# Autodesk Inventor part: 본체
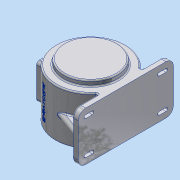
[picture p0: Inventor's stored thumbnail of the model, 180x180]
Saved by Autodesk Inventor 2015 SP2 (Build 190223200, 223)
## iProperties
Created: 2015-06
Part Number: 본체
Material: 알루미늄 6061
Document SubType Name: Modeling
Designer: AMC
Density: 2.7 g/cm^3
Appearance: 알루미늄 - 평지
Mass: 3261.98 g
Surface Area: 2301.65 cm^2
Volume: 1208.14 cm^3
Author: AMC
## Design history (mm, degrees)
sketch "스케치1"
  geometry: C1 r 85 at (0, 0); 1 further point
  constraints: 1 centre point, 1 coincident
  dimensions: "d0" = 170 diameter of C1
extrude "돌출1" new body sketch "스케치1" distance "d1" = 118; taper "d2" = 0 deg
sketch "스케치2"
  geometry: C1 r 65 at (0, 0); 1 further point
  constraints: 1 centre point, 1 coincident
  dimensions: "d3" = 130 diameter of C1
extrude "돌출2" join sketch "스케치2" distance "d4" = 13; taper "d5" = 0 deg
sketch "스케치3"
  geometry: L1 (71, -115)-(85, -115); L2 (85, -115)-(85, 115); L3 (85, 115)-(71, 115); L4 (71, 115)-(71, -115); C1 r 65 at (0, 0) reference; C2 r 85 at (0, 0) reference; C3 r 65 at (0, 0) reference; 3 further points
  constraints: 8 end point, 2 parallel, 1 coincident, 1 horizontal, 1 horizontal alignment, 1 midpoint, 1 perpendicular
  dimensions: "d6" = 230 distance of L3.end L1.start; "d7" = 14 distance of L2.end L3.end; "d8" = 85 distance from line of L2 point (0, 0)
extrude "돌출3" join sketch "스케치3" distance "d9" = 118; taper "d10" = 0 deg
node "작업 평면1"
sketch "스케치4"
  geometry: L1 (71, -115)-(71, -46.733) reference; L2 (71, 46.733)-(71, 115) reference; L3 (71, 115)-(85, 115) reference; L4 (85, 115)-(85, -115) reference; L5 (85, -115)-(71, -115) reference; L6 (71, -109)-(39.218, -97.432); A1 r 85 centre (0, 0) between (71, 46.733) and (71, -46.733) reference; 1 further point
  constraints: 2 end point, 1 point on line
  dimensions: "d11" = 6 distance from line of L5 L6.start; "d12" = 110 deg angle of L1 L6
feature "리브1" sketch "스케치4" dims "d13" = 1, "d14" = 15, "d15" = 0, "d16" = 0, "d17" = 1, "d18" = 1
node "작업 평면2"
sketch "스케치5"
  geometry: C1 r 65 at (0, 0); 1 further point
  constraints: 1 centre point, 1 coincident
  dimensions: "d19" = 130 diameter of C1
extrude "돌출4" join sketch "스케치5" distance "d20" = 3; taper "d21" = 0 deg
fillet "모깎기1" dims "d22" = 2
sketch "스케치6"
  geometry: C1 r 47.5 at (0, 0); 1 further point
  constraints: 1 centre point, 1 coincident
  dimensions: "d23" = 95 diameter of C1
extrude "돌출5" cut sketch "스케치6" distance "d24" = 11; taper "d25" = 0 deg
node "작업 평면3"
sketch "스케치7"
  geometry: L1 (-4, 118)-(14, 118) reference; L2 (14, 118)-(14, 0) reference; L3 (14, 0)-(-6, 0) reference; L4 (-6, 0)-(-6, -13) reference; L5 (-6, -13)-(-136, -13) reference; L6 (-136, -13)-(-136, 0) reference; L7 (-136, 0)-(-156, 0) reference; L8 (-156, 0)-(-156, 118) reference; L9 (-156, 118)-(-138, 118) reference; L10 (-136, 120)-(-136, 121) reference; L11 (-136, 121)-(-118.5, 121) reference; L12 (-118.5, 121)-(-118.5, 110) reference; L13 (-118.5, 110)-(-23.5, 110) reference; L14 (-23.5, 110)-(-23.5, 121) reference; L15 (-23.5, 121)-(-6, 121) reference; L16 (-6, 121)-(-6, 120) reference; L17 (-6, 121)-(-136, 121) reference; L18 (-71, -13)-(-71, 136.664); L19 (-148, 8)-(-71, 8); L20 (-71, 8)-(-71, 110); L21 (-71, 110)-(-148, 110); L22 (-148, 110)-(-148, 8); A1 r 2 centre (-4, 120) between (-6, 120) and (-4, 118) reference; A2 r 2 centre (-138, 120) between (-138, 118) and (-136, 120) reference; 1 further point
  constraints: 10 end point, 2 midpoint, 2 parallel, 1 horizontal, 1 perpendicular, 1 point on line, 1 vertical
  dimensions: "d32" = 8 distance between parallel lines of L8 L22; "d33" = 8 distance between parallel lines of L7 L19
revolve "회전1" sketch "스케치7" stored, may be unused: angle "d34" = 90 deg
sketch "스케치8"
  geometry: C1 r 31 at (0, 0); 1 further point
  constraints: 1 centre point, 1 coincident
  dimensions: "d35" = 62 diameter of C1
extrude "돌출6" join sketch "스케치8" distance "d36" = 3.5; taper "d37" = -25 deg
sketch "스케치9"
  geometry: C1 r 23.5 at (0, 0); 1 further point
  constraints: 1 centre point, 1 coincident
  dimensions: "d38" = 47 diameter of C1
extrude "돌출7" cut sketch "스케치9" distance "d39" = 14; taper "d40" = 0 deg
sketch "스케치10"
  geometry: C1 r 15 at (0, 0); 1 further point
  constraints: 1 centre point, 1 coincident
  dimensions: "d41" = 30 diameter of C1
extrude "돌출8" cut sketch "스케치10" distance "d42" = 3; taper "d43" = 0 deg
fillet "모깎기2" dims "d44" = 3
fillet "모깎기3" dims "d45" = 0.3
sketch "스케치11" dims "d46" = 110
  geometry: 3 further points
  constraints: 2 horizontal alignment, 1 coincident, 2 other
hole "구멍1" sketch "스케치11" at (55, 0) diameter "d47" = 3.242; stored, may be unused: countersink angle "d51" = 90 deg, drill point angle "d53" = 118 deg; dims "d48" = 8, "d49" = 4, "d50" = 2, "d52" = 11.8
fillet "모깎기4" dims "d57" = 18
sketch "스케치12"
  geometry: L1 (43.5, 79.201)-(43.5, 138.799) reference; L2 (43.5, 138.799)-(-58.5, 138.799) reference; L3 (-58.5, 138.799)-(-58.5, 79.201) reference; L4 (-58.5, 79.201)-(43.5, 79.201) reference; L5 (0, 0)-(-15, 0) reference; L6 (-15, 0)-(-15, 62.267) reference; L7 (-15, 62.267)-(-66.5, 62.267) reference; L8 (-66.5, 62.267)-(-66.5, 155.733) reference; L9 (-66.5, 155.733)-(-66.5, 206) reference; L10 (-48.5, 224)-(33.5, 224) reference; L11 (51.5, 206)-(51.5, 155.733) reference; L12 (51.5, 155.733)-(51.5, 62.267) reference; L13 (51.5, 62.267)-(0, 62.267) reference; L14 (0, 62.267)-(0, 0) reference; L15 (-66.5, 12)-(-66.5, 62.267) reference; L16 (33.5, -6)-(-48.5, -6) reference; L17 (51.5, 62.267)-(51.5, 12) reference; L18 (-66.5, 155.733)-(-15, 155.733) reference; L19 (-15, 155.733)-(-15, 218) reference; L20 (-15, 218)-(0, 218) reference; L21 (0, 218)-(0, 155.733) reference; L22 (0, 155.733)-(51.5, 155.733) reference; L23 (42.5, 28)-(24.5, 28); L24 (24.5, 28)-(24.5, 12); L25 (42.5, 12)-(42.5, 28); L26 (-7.5, 224)-(-7.5, -6); L27 (33.5, -6)-(-48.5, -6) reference; L28 (51.5, 109)-(-66.5, 109); L29 (-58.5, 32)-(-58.5, 186) reference; L30 (42.5, 190)-(24.5, 190); L31 (24.5, 190)-(24.5, 206); L32 (42.5, 206)-(42.5, 190); L33 (-57.5, 190)-(-39.5, 190); L34 (-39.5, 190)-(-39.5, 206); L35 (-57.5, 206)-(-57.5, 190); L36 (-57.5, 28)-(-39.5, 28); L37 (-57.5, 12)-(-57.5, 28); L38 (-39.5, 28)-(-39.5, 12); A1 r 18 centre (-48.5, 206) between (-48.5, 224) and (-66.5, 206) reference; A2 r 18 centre (33.5, 206) between (51.5, 206) and (33.5, 224) reference; A3 r 18 centre (-48.5, 12) between (-66.5, 12) and (-48.5, -6) reference; A4 r 18 centre (33.5, 12) between (33.5, -6) and (51.5, 12) reference; A5 r 9 centre (33.5, 12) between (24.5, 12) and (42.5, 12); A6 r 9 centre (33.5, 28) between (42.5, 28) and (24.5, 28); A7 r 9 centre (33.5, 206) between (42.5, 206) and (24.5, 206); A8 r 9 centre (33.5, 190) between (24.5, 190) and (42.5, 190); A9 r 9 centre (-48.5, 190) between (-57.5, 190) and (-39.5, 190); A10 r 9 centre (-48.5, 206) between (-39.5, 206) and (-57.5, 206); A11 r 9 centre (-48.5, 28) between (-39.5, 28) and (-57.5, 28); A12 r 9 centre (-48.5, 12) between (-57.5, 12) and (-39.5, 12); 4 further points
  constraints: 28 end point, 22 symmetric about line, 16 point on circle, 8 centre point, 4 coincident, 3 midpoint, 2 perpendicular, 1 horizontal, 1 parallel, 1 vertical alignment, 6 other
  dimensions: "d58" = 18 diameter of A5; "d59" = 18 diameter of A6; "d60" = 16 distance of A4.centre A6.centre; "d61" = 18 distance between parallel lines of L24 L25
extrude "돌출9" join sketch "스케치12" distance "d62" = 3; taper "d63" = 0 deg
fillet "모깎기5" dims "d64" = 3
sketch "스케치13"
  geometry: L1 (42.5, 206)-(42.5, 190) reference; L2 (24.5, 190)-(24.5, 206) reference; L3 (-57.5, 190)-(-57.5, 206) reference; L4 (-39.5, 206)-(-39.5, 190) reference; L5 (24.5, 12)-(24.5, 28) reference; L6 (42.5, 28)-(42.5, 12) reference; L7 (-39.5, 28)-(-39.5, 12) reference; L8 (-57.5, 12)-(-57.5, 28) reference; L9 (43.5, 72.875)-(43.5, 145.125) reference; L10 (43.5, 145.125)-(-58.5, 145.125) reference; L11 (-58.5, 145.125)-(-58.5, 72.875) reference; L12 (-58.5, 72.875)-(43.5, 72.875) reference; L13 (0, 1.092)-(-15, 1.092) reference; L14 (-15, 1.092)-(-15, 58) reference; L15 (-15, 58)-(-66.5, 58) reference; L16 (-66.5, 58)-(-66.5, 160) reference; L17 (-66.5, 160)-(-15, 160) reference; L18 (-15, 160)-(-15, 216.908) reference; L19 (-15, 216.908)-(0, 216.908) reference; L20 (0, 216.908)-(0, 160) reference; L21 (0, 160)-(51.5, 160) reference; L22 (51.5, 160)-(51.5, 58) reference; L23 (51.5, 58)-(0, 58) reference; L24 (0, 58)-(0, 1.092) reference; L25 (37.5, 190)-(37.5, 206); L26 (29.5, 206)-(29.5, 190); L27 (37.5, 12)-(37.5, 28); L28 (29.5, 28)-(29.5, 12); L29 (-44.5, 12)-(-44.5, 28); L30 (-52.5, 28)-(-52.5, 12); L31 (-44.5, 190)-(-44.5, 206); L32 (-52.5, 206)-(-52.5, 190); A1 r 9 centre (33.5, 206) between (42.5, 206) and (24.5, 206) reference; A2 r 9 centre (33.5, 190) between (24.5, 190) and (42.5, 190) reference; A3 r 9 centre (-48.5, 206) between (-39.5, 206) and (-57.5, 206) reference; A4 r 9 centre (-48.5, 190) between (-57.5, 190) and (-39.5, 190) reference; A5 r 9 centre (33.5, 28) between (42.5, 28) and (24.5, 28) reference; A6 r 9 centre (33.5, 12) between (24.5, 12) and (42.5, 12) reference; A7 r 9 centre (-48.5, 28) between (-39.5, 28) and (-57.5, 28) reference; A8 r 9 centre (-48.5, 12) between (-57.5, 12) and (-39.5, 12) reference; A9 r 4 centre (33.5, 206) between (37.5, 206) and (29.5, 206); A10 r 4 centre (33.5, 190) between (29.5, 190) and (37.5, 190); A11 r 4 centre (33.5, 28) between (37.5, 28) and (29.5, 28); A12 r 4 centre (33.5, 12) between (29.5, 12) and (37.5, 12); A13 r 4 centre (-48.5, 28) between (-44.5, 28) and (-52.5, 28); A14 r 4 centre (-48.5, 12) between (-52.5, 12) and (-44.5, 12); A15 r 4 centre (-48.5, 206) between (-44.5, 206) and (-52.5, 206); A16 r 4 centre (-48.5, 190) between (-52.5, 190) and (-44.5, 190); 1 further point
  constraints: 16 end point, 16 point on circle, 8 centre point, 12 other
  dimensions: "d65" = 4 radius of A10; "d66" = 4 radius of A12; "d67" = 4 radius of A14; "d68" = 4 radius of A16
extrude "돌출10" cut sketch "스케치13" stored distance "d69" = 3; taper "d70" = 0 deg
node "작업 평면4"
node "작업 평면5"
sketch "스케치14"
  geometry: L1 (-12.13, -66.5)-(-12.13, -51.5) reference; L2 (-12.13, -51.5)-(-50.267, -51.5) reference; L3 (-50.267, -51.5)-(-50.267, 0) reference; L4 (-143.733, 0)-(-50.267, 0) reference; L5 (-143.733, 0)-(-143.733, -51.5) reference; L6 (-143.733, -51.5)-(-181.87, -51.5) reference; L7 (-181.87, -51.5)-(-181.87, -66.5) reference; L8 (-181.87, -66.5)-(-143.733, -66.5) reference; L9 (-143.733, -66.5)-(-143.733, -118) reference; L10 (-50.267, -118)-(-143.733, -118) reference; L11 (-50.267, -118)-(-50.267, -66.5) reference; L12 (-50.267, -66.5)-(-12.13, -66.5) reference; L13 (-54.5, -101.5)-(-139.5, -101.5); L14 (-139.5, -101.5)-(-139.5, -16.5); L15 (-139.5, -16.5)-(-54.5, -16.5); L16 (-54.5, -16.5)-(-54.5, -101.5); 5 further points
  constraints: 8 end point, 4 midpoint, 2 parallel, 1 horizontal, 1 horizontal alignment, 1 perpendicular, 1 vertical alignment
  dimensions: "d72" = 85 distance of L14.end L15.end; "d73" = 85 distance of L13.end L14.end
extrude "돌출11" join sketch "스케치14" stored distance "d74" = 3; taper "d75" = 0 deg
fillet "모깎기6" dims "d76" = 7
sketch "스케치15"
  geometry: L1 (-23.5, 54.5)-(-94.5, 54.5) reference; L2 (-101.5, 61.5)-(-101.5, 132.5) reference; L3 (-94.5, 139.5)-(-23.5, 139.5) reference; L4 (-16.5, 132.5)-(-16.5, 61.5) reference; C1 r 35 at (-59, 97); A1 r 7 centre (-23.5, 61.5) between (-23.5, 54.5) and (-16.5, 61.5) reference; A2 r 7 centre (-94.5, 61.5) between (-101.5, 61.5) and (-94.5, 54.5) reference; A3 r 7 centre (-94.5, 132.5) between (-94.5, 139.5) and (-101.5, 132.5) reference; A4 r 7 centre (-23.5, 132.5) between (-16.5, 132.5) and (-23.5, 139.5) reference; 3 further points
  constraints: 2 midpoint, 1 centre point, 1 horizontal alignment, 1 vertical alignment
  dimensions: "d77" = 70 diameter of C1
extrude "돌출12" cut sketch "스케치15" stored distance "d78" = 3; taper "d79" = 0 deg
sketch "스케치16"
  geometry: L1 (-23.5, 54.5)-(-94.5, 54.5) reference; L2 (-101.5, 61.5)-(-101.5, 132.5) reference; L3 (-94.5, 139.5)-(-23.5, 139.5) reference; L4 (-16.5, 132.5)-(-16.5, 61.5) reference; C1 r 35 at (-59, 97) reference; A1 r 7 centre (-23.5, 61.5) between (-23.5, 54.5) and (-16.5, 61.5) reference; A2 r 7 centre (-94.5, 61.5) between (-101.5, 61.5) and (-94.5, 54.5) reference; A3 r 7 centre (-94.5, 132.5) between (-94.5, 139.5) and (-101.5, 132.5) reference; A4 r 7 centre (-23.5, 132.5) between (-16.5, 132.5) and (-23.5, 139.5) reference; 5 further points
  constraints: 4 coincident
hole "구멍2" sketch "스케치16" at (-94.5, 61.5), (-94.5, 132.5), (-23.5, 132.5), (-23.5, 61.5) diameter "d80" = 3.242; stored, may be unused: countersink angle "d84" = 90 deg, drill point angle "d86" = 118 deg; dims "d81" = 10, "d82" = 4, "d83" = 2, "d85" = 13
chamfer "모따기1" distance "d87" = 1; stored, may be unused: second distance "d88" = 2, angle "d89" = 45 deg
chamfer "모따기2" distance "d90" = 1; stored, may be unused: second distance "d91" = 2, angle "d92" = 45 deg
chamfer "모따기3" distance "d93" = 1; stored, may be unused: second distance "d94" = 2, angle "d95" = 45 deg
fillet "모깎기8" dims "d97" = 3
fillet "모깎기9" dims "d98" = 3
fillet "모깎기11" dims "d100" = 3
fillet "모깎기13" dims "d102" = 3
fillet "모깎기14" dims "d103" = 3
fillet "모깎기15" dims "d104" = 3
fillet "모깎기22" dims "d111" = 3
fillet "모깎기23" dims "d112" = 3
fillet "모깎기24" dims "d113" = 7.5
fillet "모깎기25" dims "d114" = 3
fillet "모깎기26" dims "d115" = 3
node "작업 평면8"
  node "작업 평면7"
node "작업 평면11"
  node "작업 평면10"
sketch "스케치18"
  geometry: L1 (0, 3)-(0, 115) reference; 3 further points
  constraints: 1 coincident, 1 midpoint, 1 other
feature "엠보싱2" sketch "스케치18" dims "d120" = 0.5, "d121" = 0
node "솔리드1"
mirror "대칭1"
pattern_circular "원형 패턴1" dims angle "d55" = 360 deg
node "투영된 루프1"
node "투영된 루프2"
node "작업 평면6"
node "작업 평면9"
node "절단 모서리 투영1"
node "절단 모서리 투영2"
node "절단 모서리 투영3"
node "절단 모서리 투영4"
node "절단 모서리 투영5"
node "절단 모서리 투영6"
node "절단 모서리 투영7"
node "절단 모서리 투영9"
other parameters: "d71" = -173, "d116" = 15 deg, "d119" = 205 deg
